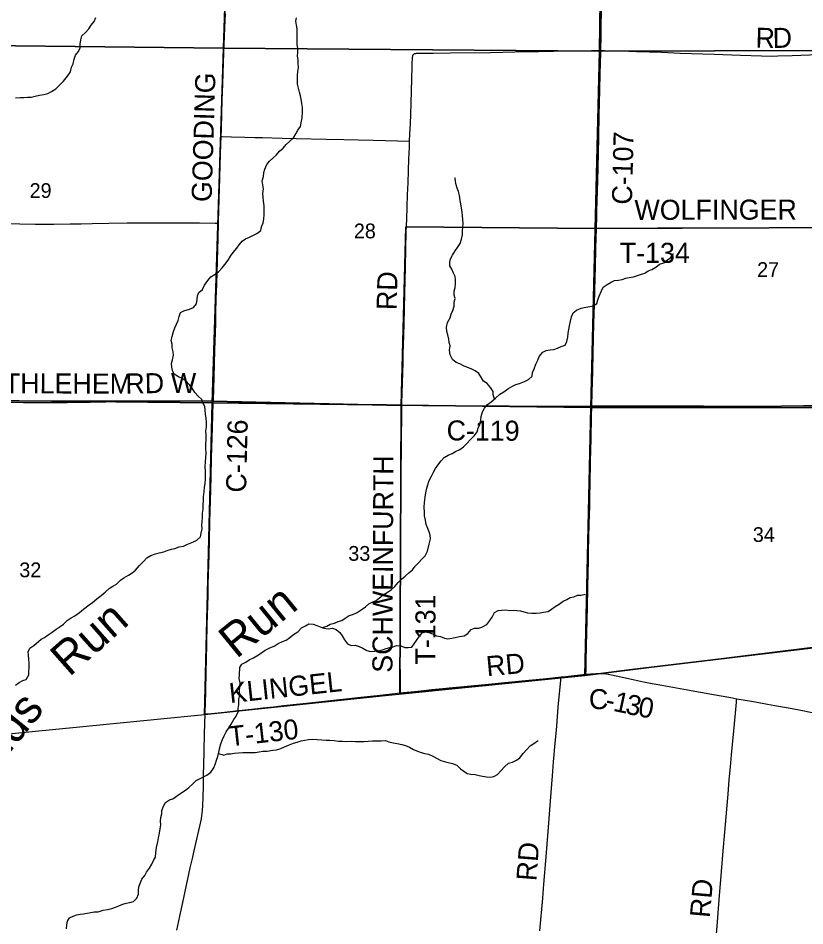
# Model space of a CAD drawing. Extents: x 1584893 to 1934202, y 663575 to 1091909.
# Drawn here: x 1784167 to 1795936, y 897514 to 911101 of the extents above; entities that cross this region are included whole.
import ezdxf

# ---------------------------------------------------------------- set-up
doc = ezdxf.new("R2010")
doc.units = 0
for name, color, linetype in [('GM_X_County_Road', 7, 'Continuous'), ('GM_X_County_Road_Text', 7, 'Continuous'), ('GM_X_Minor_River', 7, 'Continuous'), ('GM_X_Minor_River_Text', 7, 'Continuous'), ('GM_X_Section', 7, 'Continuous'), ('GM_X_Section_Text', 7, 'Continuous'), ('GM_X_Township', 7, 'Continuous'), ('GM_X_Township_Road', 7, 'Continuous'), ('GM_X_Township_Road_Text', 7, 'Continuous')]:
    doc.layers.add(name, color=color, linetype=linetype)

msp = doc.modelspace()

# ---------------------------------------------------------------- linework, layer by layer
at = {"layer": 'GM_X_County_Road'}
for points in [[(1787203, 909330), (1787207, 909446), (1787216, 909676), (1787221, 909873), (1787228, 910119), (1787239, 910430), (1787245, 910578), (1787261, 910955), (1787269, 911168)], [(1792885, 910621), (1792886, 910664), (1792888, 910796), (1792891, 910976), (1792895, 911206)], [(1792819, 907959), (1792819, 907992), (1792822, 908090), (1792825, 908222), (1792837, 908664), (1792847, 909074), (1792853, 909320), (1792861, 909648), (1792870, 910025), (1792876, 910271), (1792885, 910583), (1792885, 910621)], [(1787166, 908031), (1787166, 908052), (1787175, 908397), (1787185, 908708), (1787191, 908905), (1787200, 909217), (1787203, 909330)], [(1787087, 905370), (1787093, 905559), (1787098, 905723), (1787109, 906133), (1787117, 906396), (1787122, 906527), (1787126, 906691), (1787131, 906904), (1787137, 907117), (1787147, 907462), (1787159, 907806), (1787166, 908031)], [(1792749, 905296), (1792754, 905500), (1792762, 905812), (1792768, 906090), (1792773, 906303), (1792780, 906532), (1792788, 906812), (1792794, 907025), (1792804, 907385), (1792811, 907631), (1792816, 907828), (1792818, 907927), (1792819, 907959)], [(1783106, 905377), (1783376, 905369), (1783704, 905359), (1783819, 905355), (1784245, 905348), (1784688, 905346), (1784901, 905348), (1785246, 905353), (1785476, 905357), (1785982, 905365), (1786017, 905366), (1786329, 905372), (1786559, 905372), (1786903, 905372), (1787083, 905370), (1787087, 905370)], [(1786964, 900685), (1786965, 900705), (1786972, 901016), (1786980, 901328), (1786983, 901492), (1786990, 901738), (1786995, 902017), (1786998, 902165), (1787007, 902460), (1787011, 902607), (1787015, 902788), (1787023, 903050), (1787029, 903280), (1787035, 903559), (1787049, 904034), (1787054, 904247), (1787061, 904510), (1787065, 904674), (1787075, 904969), (1787086, 905346), (1787087, 905370)], [(1787087, 905370), (1787308, 905362), (1787534, 905355), (1787779, 905350), (1787983, 905348), (1788264, 905342), (1788481, 905339), (1788647, 905335), (1788953, 905328), (1789183, 905323), (1789363, 905319), (1789544, 905317), (1789642, 905316), (1789675, 905316), (1789909, 905311)], [(1789909, 905311), (1790216, 905305), (1790459, 905302), (1790676, 905301), (1790889, 905299), (1791109, 905297), (1791297, 905296), (1791512, 905296), (1791827, 905295), (1792300, 905294), (1792513, 905295), (1792749, 905296)], [(1792660, 901272), (1792662, 901352), (1792665, 901483), (1792673, 901910), (1792677, 902073), (1792682, 902303), (1792688, 902549), (1792693, 902828), (1792697, 902942), (1792701, 903123), (1792711, 903533), (1792717, 903795), (1792720, 903959), (1792724, 904123), (1792730, 904467), (1792734, 904631), (1792737, 904812), (1792744, 905139), (1792748, 905287), (1792749, 905296)], [(1792749, 905296), (1792816, 905297), (1793311, 905297), (1793611, 905298), (1793963, 905297), (1794422, 905296), (1795056, 905295), (1795270, 905295), (1795589, 905297), (1795914, 905303), (1796186, 905303), (1796495, 905307), (1796649, 905308)], [(1791972, 897437), (1792014, 897927), (1792033, 898139), (1792065, 898548), (1792094, 898924), (1792115, 899185), (1792141, 899512), (1792161, 899757), (1792178, 899969), (1792202, 900247), (1792220, 900443), (1792231, 900573), (1792248, 900786), (1792288, 901239)], [(1792288, 901239), (1792393, 901248), (1792506, 901257), (1792552, 901262), (1792660, 901272)], [(1792660, 901272), (1792812, 901286), (1792856, 901289), (1792861, 901290), (1792894, 901290), (1792927, 901289), (1792960, 901286), (1792993, 901281), (1793041, 901271), (1793297, 901214), (1793521, 901166), (1793650, 901141), (1793795, 901114), (1794182, 901046), (1794376, 901011), (1794569, 900976), (1794827, 900930), (1794917, 900914)], [(1794917, 900914), (1795166, 900870), (1795376, 900831), (1795489, 900812), (1795747, 900765), (1795876, 900740), (1796020, 900712), (1796230, 900671), (1796535, 900610), (1796647, 900587), (1796772, 900564)], [(1786539, 897451), (1786586, 897659), (1786632, 897865), (1786687, 898123), (1786742, 898380), (1786775, 898524), (1786800, 898636), (1786840, 898812), (1786883, 899004), (1786908, 899116), (1786917, 899164), (1786922, 899197), (1786927, 899245), (1786931, 899311), (1786936, 899442), (1786939, 899606), (1786941, 899786), (1786944, 899918), (1786950, 900131), (1786957, 900393), (1786964, 900685)]]:
    msp.add_lwpolyline(points, dxfattribs=at)
at = {"layer": 'GM_X_Minor_River'}
for points in [[(1784129, 909910), (1784197, 909913), (1784251, 909911), (1784307, 909916), (1784363, 909919), (1784423, 909932), (1784485, 909949), (1784551, 909956), (1784609, 909975), (1784667, 910003), (1784728, 910042), (1784791, 910103), (1784847, 910156), (1784904, 910233), (1784949, 910295), (1784966, 910365), (1784991, 910418), (1785006, 910486), (1785025, 910548), (1785070, 910604), (1785092, 910655), (1785093, 910710), (1785102, 910776), (1785119, 910835), (1785175, 910885), (1785226, 910942), (1785261, 910994), (1785302, 911053), (1785328, 911111)], [(1787836, 908363), (1787831, 908420), (1787826, 908474), (1787839, 908544), (1787826, 908606), (1787817, 908666), (1787838, 908732), (1787844, 908788), (1787857, 908842), (1787886, 908910), (1787927, 908961), (1787979, 909007), (1788030, 909056), (1788075, 909109), (1788129, 909157), (1788176, 909210), (1788227, 909255), (1788285, 909311), (1788322, 909370), (1788353, 909424), (1788390, 909481), (1788402, 909535), (1788417, 909609), (1788423, 909699), (1788420, 909763), (1788409, 909824), (1788400, 909886), (1788392, 909936), (1788377, 909993), (1788362, 910053), (1788347, 910111), (1788346, 910177), (1788347, 910243), (1788350, 910302), (1788362, 910362), (1788355, 910422), (1788356, 910476), (1788347, 910532), (1788352, 910594), (1788349, 910646), (1788342, 910710), (1788342, 910773), (1788339, 910831), (1788340, 910881), (1788339, 910943), (1788332, 910995), (1788321, 911054), (1788329, 911105)], [(1791294, 905403), (1791272, 905462), (1791271, 905512), (1791232, 905573), (1791185, 905631), (1791130, 905666), (1791098, 905719), (1791057, 905784), (1791002, 905823), (1790944, 905850), (1790891, 905872), (1790831, 905897), (1790774, 905926), (1790722, 905947), (1790667, 905990), (1790632, 906059), (1790619, 906133), (1790630, 906195), (1790617, 906245), (1790612, 906295), (1790593, 906360), (1790581, 906412), (1790576, 906474), (1790591, 906546), (1790630, 906614), (1790647, 906670), (1790668, 906723), (1790691, 906791), (1790692, 906851), (1790706, 906903), (1790691, 906956), (1790692, 907012), (1790703, 907068), (1790710, 907130), (1790708, 907182), (1790703, 907232), (1790678, 907282), (1790653, 907341), (1790624, 907393), (1790626, 907446), (1790635, 907499), (1790664, 907553), (1790705, 907617), (1790741, 907670), (1790780, 907726), (1790799, 907792), (1790814, 907858), (1790815, 907910), (1790820, 907972), (1790826, 908024), (1790819, 908086), (1790812, 908140), (1790811, 908204), (1790798, 908255), (1790791, 908319), (1790779, 908373), (1790769, 908447), (1790753, 908506), (1790736, 908556), (1790721, 908606), (1790712, 908657), (1790707, 908713), (1790702, 908703)], [(1786204, 903076), (1786276, 903095), (1786344, 903110), (1786397, 903131), (1786459, 903154), (1786513, 903163), (1786575, 903188), (1786639, 903197), (1786689, 903221), (1786740, 903242), (1786790, 903261), (1786842, 903288), (1786893, 903336), (1786904, 903394), (1786918, 903456), (1786915, 903512), (1786918, 903564), (1786927, 903624), (1786926, 903690), (1786933, 903752), (1786934, 903820), (1786941, 903878), (1786939, 903934), (1786951, 904014), (1786955, 904076), (1786962, 904140), (1786969, 904202), (1786971, 904318), (1786962, 904385), (1786971, 904465), (1786976, 904521), (1786977, 904587), (1786976, 904657), (1786973, 904725), (1786978, 904793), (1786977, 904867), (1786976, 904924), (1786983, 904984), (1786984, 905060), (1786980, 905110), (1786969, 905172), (1786964, 905232), (1786959, 905289), (1786932, 905343), (1786915, 905393), (1786859, 905440), (1786812, 905499), (1786771, 905562), (1786724, 905619), (1786677, 905674), (1786622, 905709), (1786564, 905731), (1786501, 905772), (1786478, 905825), (1786468, 905875), (1786461, 905931), (1786474, 905987), (1786491, 906057), (1786486, 906107), (1786473, 906168), (1786471, 906220), (1786458, 906274), (1786471, 906334), (1786490, 906410), (1786511, 906466), (1786560, 906573), (1786575, 906635), (1786594, 906693), (1786644, 906718), (1786729, 906743), (1786789, 906768), (1786834, 906824), (1786843, 906890), (1786849, 906944), (1786872, 906995), (1786923, 907039), (1786957, 907102), (1787004, 907176), (1787049, 907229), (1787114, 907268), (1787164, 907304), (1787217, 907361), (1787261, 907414), (1787308, 907480), (1787343, 907537), (1787384, 907591), (1787439, 907656), (1787473, 907710), (1787518, 907761), (1787569, 907796), (1787629, 907822), (1787687, 907851), (1787739, 907876), (1787796, 907923), (1787809, 907977), (1787832, 908037), (1787842, 908093), (1787847, 908163), (1787848, 908227), (1787845, 908293), (1787836, 908363)], [(1792589, 906759), (1792659, 906775), (1792717, 906783), (1792773, 906794), (1792824, 906831), (1792838, 906885), (1792859, 906941), (1792894, 907018), (1792919, 907072), (1792979, 907115), (1793036, 907149), (1793086, 907172), (1793146, 907179), (1793202, 907188), (1793256, 907207), (1793310, 907219), (1793374, 907230), (1793431, 907247), (1793491, 907270), (1793541, 907285), (1793593, 907320), (1793648, 907340), (1793708, 907375), (1793763, 907418), (1793825, 907439), (1793879, 907484), (1793932, 907518), (1793968, 907573), (1793970, 907571)], [(1788714, 901979), (1788784, 902001), (1788836, 902028), (1788901, 902043), (1788953, 902068), (1789009, 902083), (1789059, 902117), (1789120, 902158), (1789174, 902175), (1789240, 902202), (1789311, 902253), (1789361, 902290), (1789414, 902334), (1789464, 902359), (1789523, 902386), (1789577, 902431), (1789628, 902467), (1789688, 902504), (1789752, 902547), (1789803, 902592), (1789854, 902654), (1789904, 902701), (1789959, 902748), (1790010, 902800), (1790066, 902845), (1790107, 902898), (1790154, 902950), (1790206, 903001), (1790257, 903054), (1790290, 903120), (1790315, 903226), (1790335, 903308), (1790329, 903360), (1790314, 903410), (1790297, 903463), (1790272, 903523), (1790259, 903585), (1790248, 903650), (1790244, 903704), (1790242, 903780), (1790247, 903852), (1790256, 903930), (1790267, 903994), (1790275, 904046), (1790290, 904102), (1790317, 904180), (1790352, 904247), (1790379, 904305), (1790412, 904361), (1790446, 904412), (1790497, 904472), (1790538, 904523), (1790600, 904560), (1790659, 904583), (1790711, 904615), (1790775, 904642), (1790830, 904683), (1790884, 904738), (1790927, 904790), (1790992, 904853), (1791033, 904908), (1791051, 904964), (1791074, 905020), (1791087, 905082), (1791094, 905138), (1791113, 905206), (1791144, 905263), (1791188, 905319), (1791245, 905358), (1791306, 905413), (1791372, 905470), (1791431, 905506), (1791493, 905553), (1791560, 905594), (1791612, 905615), (1791666, 905634), (1791744, 905661), (1791803, 905694), (1791859, 905740), (1791864, 905798), (1791887, 905851), (1791910, 905921), (1791939, 905979), (1791962, 906037), (1792014, 906102), (1792065, 906127), (1792127, 906134), (1792179, 906141), (1792237, 906159), (1792291, 906184), (1792349, 906207), (1792376, 906261), (1792391, 906325), (1792394, 906385), (1792403, 906439), (1792415, 906497), (1792430, 906563), (1792447, 906630), (1792470, 906690), (1792521, 906731), (1792589, 906759)], [(1784129, 901115), (1784180, 901158), (1784236, 901185), (1784286, 901201), (1784327, 901270), (1784324, 901328), (1784329, 901378), (1784330, 901449), (1784326, 901503), (1784321, 901563), (1784318, 901615), (1784341, 901669), (1784399, 901712), (1784513, 901803), (1784563, 901832), (1784617, 901869), (1784676, 901912), (1784736, 901953), (1784795, 901995), (1784845, 902028), (1784900, 902085), (1784960, 902124), (1785017, 902156), (1785083, 902205), (1785146, 902256), (1785229, 902317), (1785281, 902352), (1785344, 902407), (1785411, 902458), (1785467, 902510), (1785528, 902563), (1785582, 902598), (1785637, 902629), (1785699, 902688), (1785750, 902724), (1785816, 902761), (1785871, 902800), (1785923, 902839), (1785980, 902907), (1786043, 902966), (1786092, 903021), (1786150, 903056), (1786204, 903076)], [(1788350, 901915), (1788406, 901974), (1788467, 902005), (1788517, 902033), (1788579, 902030), (1788633, 902007), (1788684, 901988), (1788742, 901971), (1788806, 901960), (1788868, 901969), (1788923, 901952), (1788980, 901907), (1789014, 901855), (1789047, 901796), (1789092, 901737), (1789151, 901712), (1789211, 901713), (1789269, 901693), (1789324, 901672), (1789384, 901633), (1789439, 901618), (1789502, 901627), (1789565, 901632), (1789616, 901647), (1789670, 901666), (1789726, 901680), (1789778, 901691), (1789828, 901710), (1789894, 901703), (1789950, 901682), (1790003, 901681), (1790057, 901683), (1790092, 901736), (1790137, 901798), (1790170, 901849), (1790210, 901901), (1790260, 901916), (1790312, 901907), (1790366, 901886), (1790427, 901853), (1790487, 901844), (1790543, 901822), (1790596, 901809), (1790656, 901818), (1790706, 901831), (1790771, 901844), (1790837, 901857), (1790893, 901888), (1790946, 901948), (1790996, 901969), (1791052, 901972), (1791104, 901987), (1791178, 902026), (1791221, 902084), (1791256, 902135), (1791295, 902205), (1791347, 902236), (1791399, 902240), (1791457, 902245), (1791523, 902236), (1791575, 902239), (1791627, 902232), (1791681, 902227), (1791732, 902212), (1791786, 902200), (1791854, 902193), (1791916, 902194), (1791978, 902201), (1792028, 902210), (1792094, 902219), (1792144, 902256), (1792201, 902294), (1792259, 902327), (1792320, 902372), (1792376, 902399), (1792426, 902428), (1792480, 902440), (1792533, 902463), (1792584, 902462), (1792635, 902475), (1792649, 902477)], [(1784891, 897470), (1784896, 897530), (1784907, 897582), (1784933, 897634), (1784988, 897661), (1785044, 897676), (1785094, 897688), (1785144, 897695), (1785198, 897702), (1785254, 897713), (1785304, 897722), (1785366, 897721), (1785440, 897748), (1785502, 897760), (1785568, 897773), (1785624, 897792), (1785675, 897811), (1785731, 897836), (1785783, 897853), (1785839, 897865), (1785891, 897878), (1785942, 897927), (1785967, 897987), (1785967, 898043), (1785974, 898097), (1785993, 898149), (1786016, 898211), (1786061, 898266), (1786089, 898318), (1786134, 898375), (1786169, 898435), (1786192, 898491), (1786220, 898542), (1786227, 898614), (1786238, 898684), (1786258, 898770), (1786268, 898832), (1786279, 898902), (1786292, 898968), (1786301, 899026), (1786298, 899082), (1786303, 899136), (1786314, 899190), (1786318, 899242), (1786341, 899304), (1786372, 899358), (1786430, 899401), (1786481, 899416), (1786551, 899465), (1786602, 899500), (1786670, 899546), (1786721, 899583), (1786775, 899634), (1786832, 899689), (1786932, 899740), (1786991, 899767), (1787051, 899814), (1787094, 899878), (1787119, 899942), (1787134, 899995), (1787153, 900047), (1787169, 900113), (1787180, 900165), (1787201, 900237), (1787226, 900305), (1787247, 900358), (1787278, 900416), (1787323, 900482), (1787353, 900533), (1787392, 900601), (1787429, 900652), (1787460, 900718), (1787456, 900768), (1787467, 900828), (1787470, 900902), (1787483, 900972), (1787480, 901032), (1787481, 901096), (1787486, 901150), (1787473, 901215), (1787476, 901271), (1787481, 901379), (1787514, 901431), (1787572, 901460), (1787625, 901495), (1787689, 901524), (1787739, 901557), (1787794, 901591), (1787862, 901638), (1787933, 901673), (1787997, 901702), (1788058, 901739), (1788120, 901768), (1788174, 901791), (1788233, 901828), (1788287, 901874), (1788350, 901915)], [(1787164, 900093), (1787243, 900070), (1787295, 900087), (1787349, 900088), (1787399, 900096), (1787461, 900103), (1787529, 900106), (1787583, 900107), (1787649, 900110), (1787712, 900109), (1787772, 900116), (1787827, 900127), (1787894, 900128), (1787977, 900145), (1788030, 900146), (1788095, 900167), (1788151, 900194), (1788209, 900216), (1788284, 900249), (1788340, 900264), (1788402, 900285), (1788510, 900303), (1788574, 900310), (1788638, 900303), (1788710, 900296), (1788773, 900295), (1788829, 900292), (1788893, 900287), (1788957, 900278), (1789019, 900280), (1789085, 900273), (1789159, 900279), (1789212, 900271), (1789272, 900274), (1789336, 900273), (1789404, 900278), (1789470, 900283), (1789596, 900281), (1789660, 900286), (1789713, 900269), (1789779, 900254), (1789837, 900245), (1789908, 900228), (1789962, 900211), (1790022, 900190), (1790081, 900153), (1790139, 900126), (1790196, 900109), (1790250, 900095), (1790308, 900084), (1790369, 900053), (1790435, 900018), (1790492, 899989), (1790560, 899968), (1790667, 899942), (1790731, 899917), (1790782, 899864), (1790833, 899827), (1790885, 899794), (1790940, 899786), (1791002, 899777), (1791062, 899762), (1791116, 899755), (1791171, 899742), (1791235, 899741), (1791285, 899750), (1791336, 899778), (1791392, 899839), (1791443, 899896), (1791504, 899951), (1791562, 899965), (1791620, 899992), (1791671, 900031), (1791723, 900094), (1791774, 900150), (1791825, 900209), (1791881, 900242), (1791938, 900283), (1791946, 900281)]]:
    msp.add_lwpolyline(points, dxfattribs=at)
at = {"layer": 'GM_X_Section'}
for points in [[(1782015, 916032), (1787411, 915967), (1787237, 910654), (1781905, 910709)], [(1787411, 915967), (1792936, 915937), (1792866, 910606), (1787237, 910654)], [(1792936, 915937), (1798079, 915947), (1798022, 910623), (1792866, 910606)], [(1787237, 910654), (1787071, 905345), (1781773, 905395), (1781905, 910709)], [(1792866, 910606), (1792732, 905272), (1787071, 905345), (1787237, 910654)], [(1798022, 910623), (1797981, 905272), (1792732, 905272), (1792866, 910606)], [(1787071, 905345), (1786954, 900673), (1784374, 900419), (1781625, 900145), (1781773, 905395)], [(1792732, 905272), (1792643, 901258), (1789661, 900957), (1786954, 900673), (1787071, 905345)], [(1797981, 905272), (1797947, 901914), (1795002, 901550), (1792643, 901258), (1792732, 905272)]]:
    msp.add_lwpolyline(points, close=True, dxfattribs=at)
at = {"layer": 'GM_X_Township'}
for points in [[(1796700, 907966), (1792806, 907954), (1789968, 907978), (1789895, 905305), (1787078, 905366), (1783095, 905371)], [(1796691, 901748), (1793308, 901347), (1792886, 901290), (1792653, 901274), (1792362, 901243), (1792276, 901233), (1791165, 901113), (1789877, 900998), (1789895, 905305), (1789968, 907978), (1792806, 907954), (1796700, 907966)], [(1783095, 905371), (1787078, 905366), (1789895, 905305), (1789877, 900998), (1791165, 901113), (1792276, 901233), (1792362, 901243), (1792653, 901274), (1792886, 901290), (1793308, 901347), (1796691, 901748)]]:
    msp.add_lwpolyline(points, dxfattribs=at)
at = {"layer": 'GM_X_Township_Road'}
for points in [[(1790021, 909260), (1790027, 909368), (1790034, 909517), (1790039, 909666), (1790045, 909830), (1790056, 910193), (1790061, 910375), (1790062, 910433), (1790064, 910491), (1790065, 910505), (1790066, 910513), (1790067, 910522), (1790069, 910531), (1790071, 910538), (1790073, 910545), (1790075, 910550), (1790078, 910556), (1790081, 910559), (1790088, 910565), (1790093, 910568), (1790100, 910570), (1790107, 910572), (1790116, 910574), (1790127, 910576), (1790140, 910577), (1790169, 910577), (1790382, 910577), (1790628, 910580), (1791235, 910589), (1791416, 910593), (1791596, 910596), (1791957, 910602), (1792400, 910610), (1792744, 910619), (1792875, 910621), (1792885, 910621)], [(1792885, 910621), (1792941, 910619), (1793187, 910610), (1793416, 910603), (1793793, 910590), (1794072, 910579), (1794580, 910563), (1794974, 910548), (1795285, 910537), (1795433, 910534), (1795532, 910535), (1795745, 910543), (1796007, 910551), (1796384, 910565), (1796597, 910573), (1796751, 910579)], [(1787203, 909330), (1787219, 909330), (1787359, 909325), (1787559, 909320), (1787708, 909316), (1787824, 909313), (1788117, 909305), (1788331, 909300), (1788774, 909291), (1789037, 909284), (1789480, 909272), (1789661, 909268), (1790021, 909260)], [(1789978, 907996), (1789981, 908093), (1789987, 908274), (1789993, 908454), (1789999, 908635), (1790005, 908815), (1790013, 908995), (1790015, 909077), (1790019, 909175), (1790021, 909260)], [(1783239, 908036), (1783276, 908036), (1783439, 908034), (1783653, 908031), (1783915, 908026), (1784193, 908021), (1784423, 908019), (1784702, 908018), (1784947, 908021), (1785111, 908024), (1785275, 908029), (1785521, 908032), (1785800, 908036), (1786062, 908039), (1786357, 908038), (1786669, 908036), (1786882, 908035), (1787115, 908032), (1787152, 908032), (1787166, 908031)], [(1789909, 905311), (1789909, 905338), (1789926, 905945), (1789929, 906076), (1789932, 906207), (1789940, 906519), (1789951, 906978), (1789963, 907372), (1789969, 907651), (1789974, 907897), (1789978, 907996)], [(1792819, 907959), (1792843, 907959), (1793008, 907958), (1793582, 907957), (1793664, 907958), (1793729, 907960), (1793959, 907960), (1794599, 907960), (1795025, 907962), (1795208, 907962), (1795600, 907965), (1796117, 907970), (1796322, 907972), (1796631, 907971), (1796713, 907971)], [(1789889, 901001), (1789888, 901024), (1789887, 901057), (1789886, 901204), (1789884, 901500), (1789884, 901647), (1789884, 901811), (1789884, 901975), (1789885, 902254), (1789885, 902369), (1789886, 902566), (1789889, 902828), (1789889, 903042), (1789892, 903337), (1789893, 903632), (1789895, 903927), (1789898, 904272), (1789902, 904715), (1789903, 904912), (1789905, 905043), (1789909, 905311)], [(1789889, 901001), (1789914, 901003), (1790191, 901033), (1790354, 901049), (1790518, 901065), (1790616, 901075), (1790779, 901091), (1790991, 901112), (1791204, 901131), (1791449, 901154), (1791808, 901189), (1792020, 901212), (1792168, 901228), (1792288, 901239)], [(1786964, 900685), (1786979, 900685), (1787018, 900687), (1787059, 900691), (1787255, 900714), (1787418, 900732), (1787663, 900759), (1787826, 900776), (1787989, 900794), (1788136, 900810), (1788527, 900853), (1788706, 900873), (1788886, 900893), (1789114, 900917), (1789294, 900937), (1789538, 900964), (1789889, 901001)], [(1794597, 897198), (1794629, 897574), (1794656, 897901), (1794688, 898326), (1794715, 898637), (1794741, 898915), (1794771, 899258), (1794788, 899487), (1794806, 899700), (1794824, 899896), (1794841, 900075), (1794876, 900435), (1794897, 900696), (1794912, 900860), (1794915, 900892), (1794917, 900914)]]:
    msp.add_lwpolyline(points, dxfattribs=at)

# ---------------------------------------------------------------- texts
at = {"layer": 'GM_X_County_Road_Text'}
for s, rotation, p in [('GOODING', 88.2368, (1787060, 908345)), ('C-107', 88.6228, (1793349, 908307)), ('BETHLEHEM', 359.8898, (1783418, 905485)), ('RD', 0.8872, (1785773, 905481)), ('W', 0, (1786452, 905490)), ('C-126', 88.6289, (1787576, 903997)), ('C-119', 359.7234, (1790576, 904780)), ('C', 0.2693, (1792706, 900756)), ('1', 347.8333, (1793056, 900734)), ('3', 347.8345, (1793236, 900695)), ('-', 348.5186, (1792936, 900759)), ('0', 349.4703, (1793426, 900654)), ('RD', 85.5622, (1791918, 898178))]:
    msp.add_text(s, height=300, rotation=rotation, dxfattribs=at).set_placement(p)
at = {"layer": 'GM_X_Minor_River_Text'}
for s, height, rotation, p in [('Run', 500, 39.1978, (1787431, 901501)), ('Run', 500.1, 41.4415, (1784930, 901231)), ('Davids', 500.1, 50.8734, (1783284, 899168))]:
    msp.add_text(s, height=height, rotation=rotation, dxfattribs=at).set_placement(p)
at = {"layer": 'GM_X_Section_Text'}
for s, p in [('29', (1784338, 908410)), ('28', (1789189, 907805)), ('27', (1795222, 907227)), ('34', (1795158, 903260)), ('33', (1789106, 902978)), ('32', (1784184, 902732))]:
    msp.add_text(s, height=221, rotation=0, dxfattribs=at).set_placement(p)
at = {"layer": 'GM_X_Township_Road_Text'}
for s, rotation, p in [('R', 358.669, (1795196, 910659)), ('D', 1.1549, (1795457, 910654)), ('WOLFINGER', 0.1165, (1793387, 908081)), ('T-134', 0, (1793167, 907438)), ('RD', 88.5193, (1789828, 906728)), ('SCHWEINFURTH', 89.7376, (1789766, 901302)), ('T-131', 90, (1790410, 901425)), ('RD', 5.3261, (1791182, 901248)), ('KLINGEL', 6.1321, (1787338, 900847)), ('T-130', 6.3706, (1787333, 900199)), ('RD', 85.0701, (1794514, 897627))]:
    msp.add_text(s, height=300, rotation=rotation, dxfattribs=at).set_placement(p)

doc.saveas('drawing.dxf')
